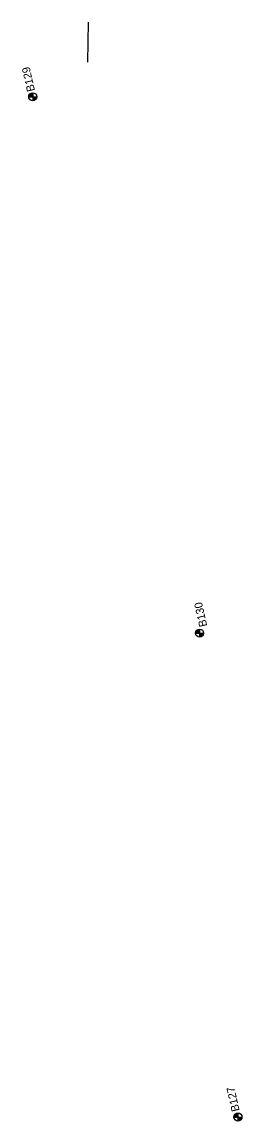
# Model space of a CAD drawing. Extents: x 331323 to 388339, y 121519 to 205315.
# Drawn here: x 355874 to 356149, y 199471 to 200845 of the extents above; entities that cross this region are included whole.
import ezdxf

# ---------------------------------------------------------------- set-up
doc = ezdxf.new("R2010")
doc.units = 0
for name, color, linetype in [('E_SOIL_BORE1 [KAPUR_CADDS_LEVELS]', 7, 'Continuous'), ('E_SOIL_BORE2 [KAPUR_CADDS_LEVELS]', 7, 'Continuous'), ('Level 57', 7, 'Continuous'), ('P_MARK', 7, 'Continuous')]:
    doc.layers.add(name, color=color, linetype=linetype)

msp = doc.modelspace()

# ---------------------------------------------------------------- linework, layer by layer
at = {"layer": 'Level 57'}
msp.add_lwpolyline([(355956.9, 200795), (355957.4, 200845)], dxfattribs=at)
at = {"layer": 'P_MARK'}
for p, q in [((355882.8, 200751.6), (355892.8, 200751.6)), ((355887.8, 200756.6), (355887.8, 200746.6)), ((356096.4, 200086.2), (356096.4, 200076.2)), ((356091.4, 200081.2), (356101.4, 200081.2)), ((356139.4, 199476.4), (356149.4, 199476.4)), ((356144.4, 199481.4), (356144.4, 199471.4))]:
    msp.add_line(p, q, dxfattribs=at)
for centre in [(355887.8, 200751.6), (356096.4, 200081.2), (356144.4, 199476.4)]:
    msp.add_circle(centre, 5, dxfattribs=at)
for centre, radius, start, end in [((355887.8, 200751.6), 4.5, 89.9869, 179.9869), ((355887.8, 200751.6), 4, 89.9869, 179.9869), ((355887.8, 200751.6), 3.5, 89.9869, 179.9869), ((355887.8, 200751.6), 3, 89.9869, 179.9869), ((355887.8, 200751.6), 2.5, 89.9869, 179.9869), ((355887.8, 200751.6), 2, 89.9869, 179.9869), ((355887.8, 200751.6), 1.5, 89.9869, 179.9869), ((355887.8, 200751.6), 1, 89.9869, 179.9869), ((355887.8, 200751.6), 0.5, 89.9869, 179.9869), ((355887.8, 200751.6), 4.5, 269.9869, 359.9869), ((355887.8, 200751.6), 4, 269.9869, 359.9869), ((355887.8, 200751.6), 3.5, 269.9869, 359.9869), ((355887.8, 200751.6), 3, 269.9869, 359.9869), ((355887.8, 200751.6), 2.5, 269.9869, 359.9869), ((355887.8, 200751.6), 2, 269.9869, 359.9869), ((355887.8, 200751.6), 1.5, 269.9869, 359.9869), ((355887.8, 200751.6), 1, 269.9869, 359.9869), ((355887.8, 200751.6), 0.5, 269.9869, 359.9869), ((356096.4, 200081.2), 4.5, 89.9869, 179.9869), ((356096.4, 200081.2), 4, 89.9869, 179.9869), ((356096.4, 200081.2), 3.5, 89.9869, 179.9869), ((356096.4, 200081.2), 3, 89.9869, 179.9869), ((356096.4, 200081.2), 2.5, 89.9869, 179.9869), ((356096.4, 200081.2), 2, 89.9869, 179.9869), ((356096.4, 200081.2), 1.5, 89.9869, 179.9869), ((356096.4, 200081.2), 1, 89.9869, 179.9869), ((356096.4, 200081.2), 0.5, 89.9869, 179.9869), ((356096.4, 200081.2), 4.5, 269.9869, 359.9869), ((356096.4, 200081.2), 4, 269.9869, 359.9869), ((356096.4, 200081.2), 3.5, 269.9869, 359.9869), ((356096.4, 200081.2), 3, 269.9869, 359.9869), ((356096.4, 200081.2), 2.5, 269.9869, 359.9869), ((356096.4, 200081.2), 2, 269.9869, 359.9869), ((356096.4, 200081.2), 1.5, 269.9869, 359.9869), ((356096.4, 200081.2), 1, 269.9869, 359.9869), ((356096.4, 200081.2), 0.5, 269.9869, 359.9869), ((356144.4, 199476.4), 4.5, 89.9869, 179.9869), ((356144.4, 199476.4), 4, 89.9869, 179.9869), ((356144.4, 199476.4), 3.5, 89.9869, 179.9869), ((356144.4, 199476.4), 3, 89.9869, 179.9869), ((356144.4, 199476.4), 2.5, 89.9869, 179.9869), ((356144.4, 199476.4), 2, 89.9869, 179.9869), ((356144.4, 199476.4), 1.5, 89.9869, 179.9869), ((356144.4, 199476.4), 1, 89.9869, 179.9869), ((356144.4, 199476.4), 0.5, 89.9869, 179.9869), ((356144.4, 199476.4), 4.5, 269.9869, 359.9869), ((356144.4, 199476.4), 4, 269.9869, 359.9869), ((356144.4, 199476.4), 3.5, 269.9869, 359.9869), ((356144.4, 199476.4), 3, 269.9869, 359.9869), ((356144.4, 199476.4), 2.5, 269.9869, 359.9869), ((356144.4, 199476.4), 2, 269.9869, 359.9869), ((356144.4, 199476.4), 1.5, 269.9869, 359.9869), ((356144.4, 199476.4), 1, 269.9869, 359.9869), ((356144.4, 199476.4), 0.5, 269.9869, 359.9869)]:
    msp.add_arc(centre, radius, start, end, dxfattribs=at)

# ---------------------------------------------------------------- texts
at = {"layer": 'E_SOIL_BORE1 [KAPUR_CADDS_LEVELS]'}
msp.add_text('B127', height=10, rotation=102.6348, dxfattribs=at).set_placement((356146.5, 199484.4))
at = {"layer": 'E_SOIL_BORE2 [KAPUR_CADDS_LEVELS]'}
for s, p in [('B129', (355890.7, 200759.2)), ('B130', (356106, 200090.2))]:
    msp.add_text(s, height=10, rotation=102.6348, dxfattribs=at).set_placement(p)

doc.saveas('drawing.dxf')
